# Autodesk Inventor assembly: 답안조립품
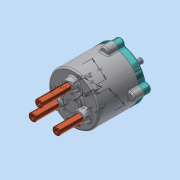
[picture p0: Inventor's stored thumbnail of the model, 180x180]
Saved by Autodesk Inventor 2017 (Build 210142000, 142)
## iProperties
Part Number: 답안조립품
Material: 일반
Document SubType Name: Assembly
Designer: MRC
Mass: 1236.63 g
Surface Area: 1770.12 cm^2
Volume: 433.788 cm^3
Density: 2.85078 g/cm^3
Author: MRC
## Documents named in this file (14)
- C:\Users\MRC\Desktop\610708V1005\답안조립품.iam
- C:\Users\MRC\Desktop\610708V1005\본체.ipt
- C:\Users\MRC\Desktop\610708V1005\가변스프링1.ipt
- C:\Users\MRC\Desktop\610708V1005\가변스프링2.ipt
- C:\Users\MRC\Desktop\610708V1005\가변스프링3.ipt
- C:\Users\MRC\Desktop\610708V1005\멈춤링 10 x 1.ipt
- C:\Users\MRC\Desktop\610708V1005\멈춤링 22 x 1.2.ipt
- C:\Users\MRC\Desktop\610708V1005\메인 축.ipt
- C:\Users\MRC\Desktop\610708V1005\베어링 NA 4900.ipt
- C:\Users\MRC\Desktop\610708V1005\볼트 M5.ipt
- C:\Users\MRC\Desktop\610708V1005\슬라이드 축.ipt
- C:\Users\MRC\Desktop\610708V1005\오일실.ipt
- C:\Users\MRC\Desktop\610708V1005\커버.ipt
- C:\Users\MRC\Desktop\610708V1005\판캠.ipt
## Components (3 placed, 3 different names)
1. 가변스프링1:1
2. 가변스프링2:1
3. 가변스프링3:1
